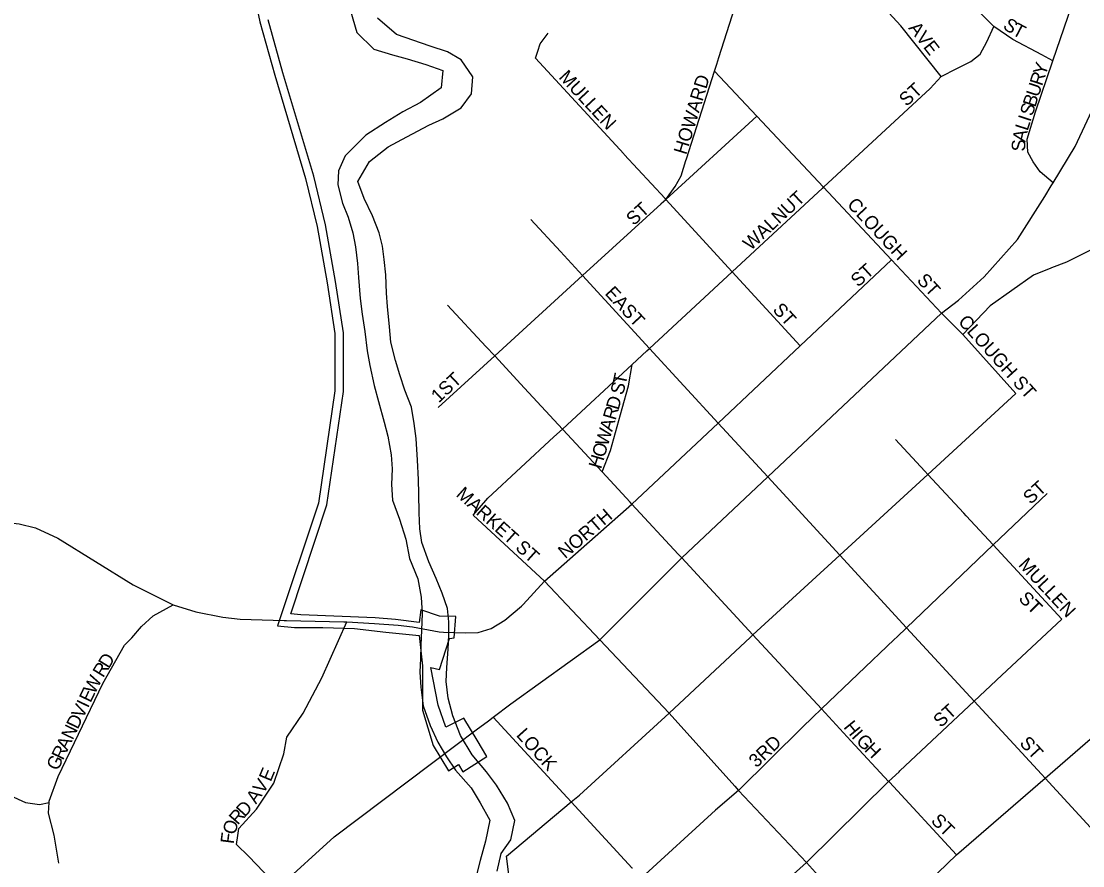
# Model space of a CAD drawing. Extents: x 1578669 to 1989827, y 208020 to 553079.
# Drawn here: x 1828673 to 1832626, y 409962 to 413109 of the extents above; entities that cross this region are included whole.
import ezdxf

# ---------------------------------------------------------------- set-up
doc = ezdxf.new("R2010")
doc.units = 0
for name, color, linetype in [('GM_X_City_Street', 7, 'Continuous'), ('GM_X_City_Street_Text', 7, 'Continuous'), ('GM_X_Corporation', 7, 'Continuous'), ('GM_X_Minor_River', 7, 'Continuous'), ('GM_X_State_Route', 7, 'Continuous'), ('GM_X_US_Route', 7, 'Continuous')]:
    doc.layers.add(name, color=color, linetype=linetype)

msp = doc.modelspace()

# ---------------------------------------------------------------- linework, layer by layer
at = {"layer": 'GM_X_City_Street'}
for points in [[(1832515.3, 412960.9), (1832473.6, 412983.6), (1832366, 413041), (1832295.7, 413089.6), (1832187.5, 413199.7), (1832112.4, 413286.8), (1832013.4, 413386.3), (1831936.3, 413477.5), (1831883, 413540.3), (1831854.2, 413646.9), (1831835.1, 413725.4), (1831829.1, 413799.1), (1831810.2, 413827.9), (1831763, 413896.7), (1831734.5, 413932.6), (1831644, 414002.4), (1831601, 414036)], [(1832515.9, 412507.1), (1832467.7, 412548.2), (1832442, 412584.6), (1832422.4, 412620.9), (1832419, 412669.1), (1832450.3, 412770.9), (1832515.3, 412960.9), (1832599.8, 413207.9), (1832661, 413457.7), (1832696.8, 413603.5), (1832687.9, 413691.9), (1832659.1, 413798.5), (1832619.8, 413869.1), (1832556.3, 413924), (1832494.7, 413971)], [(1832099.1, 412903.4), (1831948.9, 413092), (1831681.8, 413382.1), (1831640.3, 413436.7), (1831624.7, 413475), (1831623.3, 413519.1), (1831639, 413661.2), (1831734.5, 413932.6)], [(1831271.3, 412974.2), (1831410.7, 413412.8), (1831416.9, 413432.3)], [(1830918.8, 412612.7), (1830917.3, 412614.3), (1830588.3, 412971.2), (1830596.6, 412997.1), (1830605, 413025.1), (1830635.5, 413064.8)], [(1831657, 412486.4), (1831657.9, 412487.3), (1831661, 412490.2), (1832058.4, 412858.1), (1832099.1, 412903.4), (1832157.5, 412933), (1832210, 412958.4), (1832244.4, 412986), (1832269, 413031.8), (1832295.7, 413089.6)], [(1831150.5, 412596.5), (1831255.1, 412923.3), (1831263.3, 412949.1), (1831271.3, 412974.2)], [(1832100.5, 412021.3), (1831914.1, 412220.2), (1831661, 412490.2), (1831412.7, 412755.1), (1831255.1, 412923.3)], [(1831056.6, 412429.3), (1831073.6, 412444.8), (1831412.7, 412755.1)], [(1831573.4, 411899.2), (1831320.7, 412175), (1831073.6, 412444.8), (1831070.9, 412447.7), (1830918.8, 412612.7)], [(1831073.6, 412444.8), (1831107.8, 412493.5), (1831130.3, 412533.3), (1831148.4, 412589.8), (1831150.5, 412596.5)], [(1831002.8, 411880.7), (1831003.3, 411881.1), (1831012.8, 411889.9), (1831320.7, 412175), (1831657, 412486.4)], [(1830225.8, 411669), (1830436.2, 411861.5), (1830763.4, 412161), (1831055.9, 412428.6), (1831056.6, 412429.3)], [(1830680.7, 412250.9), (1830680.7, 412250.9), (1830571, 412370.1)], [(1832472.1, 410303.2), (1832221.8, 410575.3), (1831970.1, 410849), (1831721.2, 411119.6), (1831453.1, 411411.1), (1831268.5, 411611.8), (1831012.8, 411889.9), (1830763.4, 412161), (1830680.7, 412250.9)], [(1830621.1, 411022.8), (1830947.3, 411309.2), (1831268.5, 411611.8), (1831573.4, 411899.2), (1831914.1, 412220.2)], [(1830403.6, 411896.8), (1830403.6, 411896.8), (1830260.5, 412051.4)], [(1832377.6, 411721.6), (1832179.6, 411941.7)], [(1830546.7, 411742.2), (1830436.2, 411861.5), (1830403.6, 411896.8)], [(1830656.5, 411560), (1830656.7, 411560.1), (1830688.2, 411589.3), (1830947.5, 411829.4), (1831002.8, 411880.7)], [(1830836.3, 411429.3), (1830867.4, 411509.5), (1830910.7, 411665.4), (1830934.5, 411750.1), (1830947.5, 411829.4)], [(1830491, 409908.2), (1830490.8, 409909.9), (1830480.5, 409998.1), (1830721.5, 410199.8), (1830751.8, 410225.1), (1831086, 410530.7), (1831388.4, 410814.3), (1831397.6, 410822.7), (1831721.2, 411119.6), (1832049.2, 411420.4), (1832377.6, 411721.6)], [(1830689.8, 411587.5), (1830688.2, 411589.3), (1830546.7, 411742.2), (1830546.7, 411742.2)], [(1830355.4, 411268.5), (1830410.2, 411331.9), (1830656.5, 411560)], [(1830940.2, 411316.9), (1830836.3, 411429.3), (1830689.8, 411587.5)], [(1832049.2, 411420.4), (1832037.8, 411432.8), (1831928.5, 411550.9)], [(1832191.7, 411266.5), (1832183.5, 411275.3), (1832049.2, 411420.4)], [(1831119.1, 411123.7), (1830947.3, 411309.2), (1830940.2, 411316.9), (1830940.2, 411316.9)], [(1831935.1, 410815.6), (1831970.1, 410849), (1832292.7, 411157.4), (1832493.4, 411349.2)], [(1830621.1, 411022.8), (1830355.4, 411268.5)], [(1832547.9, 410881.5), (1832292.7, 411157.4), (1832191.7, 411266.5)], [(1831763, 410427.9), (1831653.4, 410546.3), (1831397.6, 410822.7), (1831132.6, 411109), (1831119.1, 411123.7), (1831119.1, 411123.7)], [(1828812.2, 409971.4), (1828795.4, 410075.9), (1828774.3, 410158.3), (1828776.6, 410198.2), (1828776.9, 410202.4), (1828810.1, 410294.2), (1828976.6, 410640.8), (1829057.7, 410783.7), (1829084.2, 410811.3), (1829120.2, 410853.6), (1829163.6, 410893.9), (1829238.8, 410934.2)], [(1832303.3, 410651.9), (1832305.6, 410654), (1832547.9, 410881.5)], [(1829630.3, 409881.1), (1829520.2, 409996.4), (1829474.6, 410041.1), (1829479, 410075.1), (1829483.3, 410101.1), (1829548.3, 410172.4), (1829613.7, 410269.8), (1829651.1, 410379.6), (1829661.8, 410441.6), (1829723, 410531), (1829792.8, 410662.4), (1829885.5, 410870.8)], [(1831620.2, 410514.6), (1831653.4, 410546.3), (1831923.7, 410804.7), (1831935.1, 410815.6)], [(1827705.4, 410629.1), (1827914.5, 410674.5), (1828191.5, 410705), (1828291.8, 410705.7), (1828352, 410715), (1828386, 410712.5), (1828410, 410704.2), (1828429.9, 410691.9), (1828459.6, 410657.4), (1828521.4, 410462.2), (1828556.2, 410359.6), (1828579.5, 410297.1), (1828605, 410246.7), (1828630.8, 410224.3), (1828688.6, 410197.5), (1828740.7, 410190.8), (1828776.6, 410198.2)], [(1831945.2, 410315.5), (1832221.8, 410575.3), (1832303.3, 410651.9)], [(1830707.1, 410215.5), (1830706.6, 410216), (1830430.7, 410515.8)], [(1831344.4, 410242.7), (1831581.9, 410478), (1831620.2, 410514.6)], [(1831823.3, 409682.2), (1831842.7, 409701.1), (1832156.5, 410002.7), (1832485.8, 410288.3), (1832728.3, 410498.6), (1832736.6, 410505.8)], [(1831906.1, 410273.2), (1831903.3, 410276.2), (1831763, 410427.9), (1831763, 410427.9)], [(1830911.7, 409357.4), (1831231.6, 409645.4), (1831597.9, 409974.4), (1831903.3, 410276.2), (1831942.1, 410312.7), (1831945.2, 410315.5)], [(1832654.9, 410104.5), (1832485.8, 410288.3), (1832472.1, 410303.2), (1832472.1, 410303.2)], [(1832156.5, 410002.7), (1831906.1, 410273.2), (1831906.1, 410273.2)], [(1830948.9, 409952.7), (1830948.5, 409953.1), (1830721.5, 410199.8), (1830707.1, 410215.5)], [(1832348.2, 409068.9), (1832318.9, 409099.5), (1832042.7, 409388.3), (1831842.7, 409701.1), (1831597.9, 409974.4), (1831344.4, 410242.7)]]:
    msp.add_lwpolyline(points, dxfattribs=at)
at = {"layer": 'GM_X_Corporation'}
msp.add_lwpolyline([(1829519.5, 413306.5), (1829561.1, 413106.8), (1829616.7, 412907.7), (1829731.3, 412523.3), (1829774.5, 412343.8), (1829811.7, 412134.2), (1829840.9, 411945.3), (1829840.3, 411731.4), (1829779.5, 411313.7), (1829627.6, 410855.8), (1829690.1, 410849.7), (1829796.5, 410849.7), (1829913.9, 410846), (1830030.1, 410832.4), (1830155, 410820.1), (1830166.8, 410706.5), (1830166.8, 410542), (1830207, 410410.5), (1830263.6, 410316.2), (1830301, 410339.6), (1830317.3, 410312.6), (1830407, 410368.7), (1830370.2, 410430), (1830321, 410511.9), (1830253.6, 410479), (1830225.5, 410560.5), (1830198.4, 410700.3), (1830230.2, 410692.9), (1830267.5, 410808.9), (1830285, 410811.5), (1830291, 410890.6), (1830230.4, 410891.8), (1830161.2, 410915.3), (1830154.3, 410868.5), (1830067.2, 410879.4), (1829990.6, 410885.6), (1829713.6, 410896.7), (1829676.4, 410901.3), (1829810.7, 411306.3), (1829872.3, 411729.1), (1829872.9, 411947.7), (1829843.3, 412139.4), (1829805.8, 412350.4), (1829762.2, 412531.6), (1829647.4, 412916.6), (1829592.2, 413114.4)], dxfattribs=at)
at = {"layer": 'GM_X_Minor_River'}
for points in [[(1829899.5, 413147.7), (1829922.6, 413067.2), (1829985.9, 413004.4), (1830055.7, 412983.5), (1830109.6, 412968.9), (1830179.4, 412948), (1830243.2, 412925.3), (1830236.4, 412861.2), (1830159.8, 412806), (1830093.3, 412770.7), (1830028.8, 412731.4), (1829956.3, 412684.1), (1829879.4, 412606.9), (1829854.7, 412551), (1829852.1, 412499), (1829869.4, 412430.6), (1829890.8, 412378.3), (1829908.1, 412320), (1829917.5, 412267.8), (1829924.8, 412205.6), (1829928.2, 412153.4), (1829935.3, 412075.2), (1829942.7, 412017), (1829952, 411952.8), (1829961.1, 411880.5), (1829970.5, 411826.3), (1829987.7, 411752), (1830003, 411691.7), (1830024.2, 411615.3), (1830037.6, 411563), (1830050.8, 411492.8), (1830054.2, 411440.6), (1830051.5, 411382.5), (1830054.9, 411324.4), (1830082.1, 411253.9), (1830105.2, 411179.5), (1830118.4, 411107.2), (1830149.6, 411030.7), (1830162.8, 410962.5), (1830166.1, 410902.3), (1830163.4, 410840.2), (1830160.8, 410784.1), (1830160.2, 410734), (1830157.6, 410684), (1830161, 410627.8), (1830170.2, 410557.6), (1830195.4, 410485.2), (1830224.7, 410422.7), (1830256.1, 410368.2), (1830289.5, 410317.8), (1830348.8, 410253), (1830382.2, 410196.5), (1830417.5, 410131.9)], [(1830496.7, 410058.9), (1830511.5, 410130.8), (1830484.2, 410195.3), (1830442.9, 410261.9), (1830405.5, 410312.4), (1830352.2, 410375.1), (1830309, 410447.8), (1830279.8, 410520.3), (1830262.6, 410586.6), (1830255.3, 410648.8), (1830257.9, 410700.9), (1830262.6, 410768.9), (1830265.2, 410821), (1830265.8, 410871.1), (1830260.4, 410921.2), (1830241, 410977.6), (1830217.6, 411032), (1830190.3, 411094.4), (1830165.1, 411166.8), (1830157.7, 411217), (1830154.4, 411277.1), (1830153.2, 411347.3), (1830151.8, 411401.4), (1830148.6, 411473.6), (1830143.5, 411553.8), (1830136.1, 411610), (1830126.8, 411670.2), (1830101.5, 411734.6), (1830082.2, 411791), (1830066.8, 411845.2), (1830049.6, 411913.6), (1830044.2, 411969.7), (1830037.1, 412046), (1830033.6, 412096.1), (1830030.4, 412164.3), (1830025, 412220.4), (1830017.6, 412270.6), (1830006.2, 412320.8), (1829980.9, 412383.2), (1829949.6, 412447.7), (1829926.3, 412512.1), (1829969.2, 412585.8), (1830039.8, 412641.1), (1830108.3, 412678.3), (1830190.8, 412721.5), (1830243.1, 412744.9), (1830311.6, 412786.2), (1830350.2, 412837.9), (1830354.9, 412901.9), (1830311.6, 412964.6), (1830260, 412995.2), (1830196.2, 413016), (1830070.6, 413059.5), (1829999.3, 413120.5)], [(1830417.5, 410131.9), (1830401.6, 410053.5), (1830382.3, 409981.7), (1830367.2, 409923.9)], [(1830445.5, 409942.5), (1830460.7, 410008.3), (1830496.7, 410058.9)]]:
    msp.add_lwpolyline(points, dxfattribs=at)
at = {"layer": 'GM_X_State_Route'}
for points in [[(1832985.8, 412424.1), (1832975.2, 412418.2), (1832965.9, 412413.1), (1832915.9, 412387.9), (1832565.7, 412211.5), (1832510.5, 412189.6)], [(1832510.5, 412189.6), (1832507, 412188.2), (1832443.5, 412163), (1832281.5, 412048.3), (1832179.6, 411941.7), (1832100.5, 412021.3)], [(1828568.9, 411238.8), (1828606.7, 411242.8), (1828665, 411236.7), (1828725.8, 411220.9), (1828808.5, 411183.2), (1829089.5, 411009.4), (1829238.8, 410934.2), (1829322.5, 410908.7), (1829423.2, 410888.6), (1829487.8, 410881.2), (1829651.8, 410875.7), (1829660.1, 410875.5)], [(1830535.6, 410929.6), (1830542, 410935.1), (1830621.1, 411022.8), (1830827.6, 410804)], [(1830245.4, 410833.1), (1830326.9, 410830), (1830373.9, 410831.2), (1830423.3, 410846), (1830474, 410877), (1830535.6, 410929.6)], [(1829660.1, 410875.5), (1829873.8, 410871)], [(1829873.8, 410871), (1829885.5, 410870.8), (1829988.1, 410864.6), (1830077.1, 410858.4), (1830130.3, 410852.2), (1830229.2, 410833.7), (1830245.4, 410833.1)], [(1830827.6, 410804), (1830827.6, 410804), (1831086, 410530.7), (1831330.2, 410258.5)], [(1831330.2, 410258.5), (1831344.4, 410242.7), (1831258.4, 410169.6), (1830982.2, 409916.5), (1830807.2, 409762.7)]]:
    msp.add_lwpolyline(points, dxfattribs=at)
at = {"layer": 'GM_X_US_Route'}
for points in [[(1832100.5, 412021.3), (1832163.2, 412070), (1832259.1, 412156.5), (1832383, 412295.2), (1832484.8, 412455.9), (1832509.1, 412495.9), (1832515.9, 412507.1), (1832598.4, 412642.6), (1832696, 412851.4), (1832769.5, 413078.2), (1832828.7, 413395.2), (1832840.6, 413530.8), (1832881.1, 413994.8), (1832881.3, 414000.1), (1832881.5, 414002.3)], [(1830827.6, 410804), (1831132.6, 411109), (1831453.1, 411411.1), (1832100.5, 412021.3)], [(1830367.1, 410468), (1830412.6, 410502.2), (1830430.7, 410515.8), (1830496.4, 410565.3), (1830827.6, 410804)], [(1830291.2, 410410.9), (1830367.1, 410468)], [(1829378.9, 409652.6), (1829398.9, 409670.8), (1829401, 409672.7), (1829599.4, 409853.1), (1829630.3, 409881.1), (1829838.7, 410070.5), (1830291.2, 410410.9)]]:
    msp.add_lwpolyline(points, dxfattribs=at)

# ---------------------------------------------------------------- texts
at = {"layer": 'GM_X_City_Street_Text'}
for s, rotation, p in [('AVE', 308.045, (1831975.1, 413082.6)), ('S', 325.2945, (1832325.5, 413084.3)), ('T', 332.3071, (1832360.1, 413060.8)), ('Y', 72.1198, (1832487.1, 412903)), ('MULLEN', 312.8801, (1830672.2, 412898.4)), ('HOWARD', 73.032, (1831149.1, 412608.8)), ('R', 72.1027, (1832474.9, 412865.3)), ('ST', 42.5121, (1831970.1, 412789)), ('U', 72.0971, (1832461.4, 412823.5)), ('B', 72.1027, (1832449.2, 412785.8)), ('S', 72.1271, (1832438.4, 412752.3)), ('I', 72.0904, (1832431.6, 412731.3)), ('A', 77.9999, (1832412.2, 412656.1)), ('L', 72.4031, (1832421, 412697.8)), ('S', 88.3876, (1832411.5, 412623.2)), ('WALNUT', 42.9797, (1831389.3, 412252.1)), ('ST', 42.5022, (1830953.7, 412344.6)), ('CLOUGH', 312.9311, (1831745.8, 412423.2)), ('ST', 42.2757, (1831789.8, 412115.8)), ('ST', 312.5022, (1832005.5, 412141.6)), ('EAST', 312.7063, (1830843.8, 412093.2)), ('ST', 312.5121, (1831468.7, 412031.6)), ('CLOUGH ST', 311.8775, (1832159.5, 411987.5)), ('1ST', 43.2587, (1830227.7, 411684.5)), ('T', 78.4328, (1830923.9, 411751)), ('S', 74.4423, (1830913.5, 411713.4)), ('D', 73.5352, (1830897.1, 411657.7)), ('R', 73.5543, (1830885.9, 411619.7)), ('W', 73.5479, (1830857.2, 411522.7)), ('A', 73.5533, (1830873.4, 411577.6)), ('O', 73.5352, (1830844.7, 411480.5)), ('H', 73.5562, (1830832.3, 411438.3)), ('ST', 42.5022, (1832432.1, 411306.2)), ('MARKET ST', 318.1204, (1830288.8, 411341.4)), ('NORTH', 40.7315, (1830698.8, 411104)), ('MULLEN', 312.9311, (1832383.8, 411081.2)), ('ST', 315.0099, (1832384.3, 410954.6)), ('D', 58.2379, (1828998.5, 410693.9)), ('R', 58.3989, (1828977.8, 410660.2)), ('W', 63.232, (1828946, 410598.6)), ('E', 64.3463, (1828930.8, 410567.1)), ('V', 64.3243, (1828902.2, 410507.6)), ('I', 64.3148, (1828921.3, 410547.3)), ('ST', 42.5022, (1832097.7, 410474.6)), ('D', 64.344, (1828883.2, 410468)), ('N', 64.344, (1828864.1, 410428.3)), ('H', 309.1787, (1831733.1, 410477.8)), ('LOCK', 311.7622, (1830513.9, 410447.5)), ('I', 312.0078, (1831762.7, 410441.7)), ('G', 314.6487, (1831779.1, 410423.5)), ('R', 64.3257, (1828827.9, 410352.9)), ('A', 64.3514, (1828845.1, 410388.6)), ('3RD', 43.4467, (1831411.2, 410324.9)), ('H', 314.9992, (1831810.3, 410391.9)), ('ST', 312.5121, (1832388.2, 410416.8)), ('G', 64.344, (1828808.8, 410313.3)), ('E', 67.3542, (1829601.9, 410272.7)), ('V', 56.8938, (1829573.2, 410227)), ('A', 55.0821, (1829547, 410189.5)), ('R', 48.7981, (1829479.1, 410111.5)), ('D', 47.8601, (1829505.1, 410141.1)), ('O', 71.1988, (1829467.5, 410074.3)), ('ST', 315, (1832058, 410126.7)), ('F', 82.5768, (1829463.6, 410041.9))]:
    msp.add_text(s, height=50, rotation=rotation, dxfattribs=at).set_placement(p)

doc.saveas('drawing.dxf')
